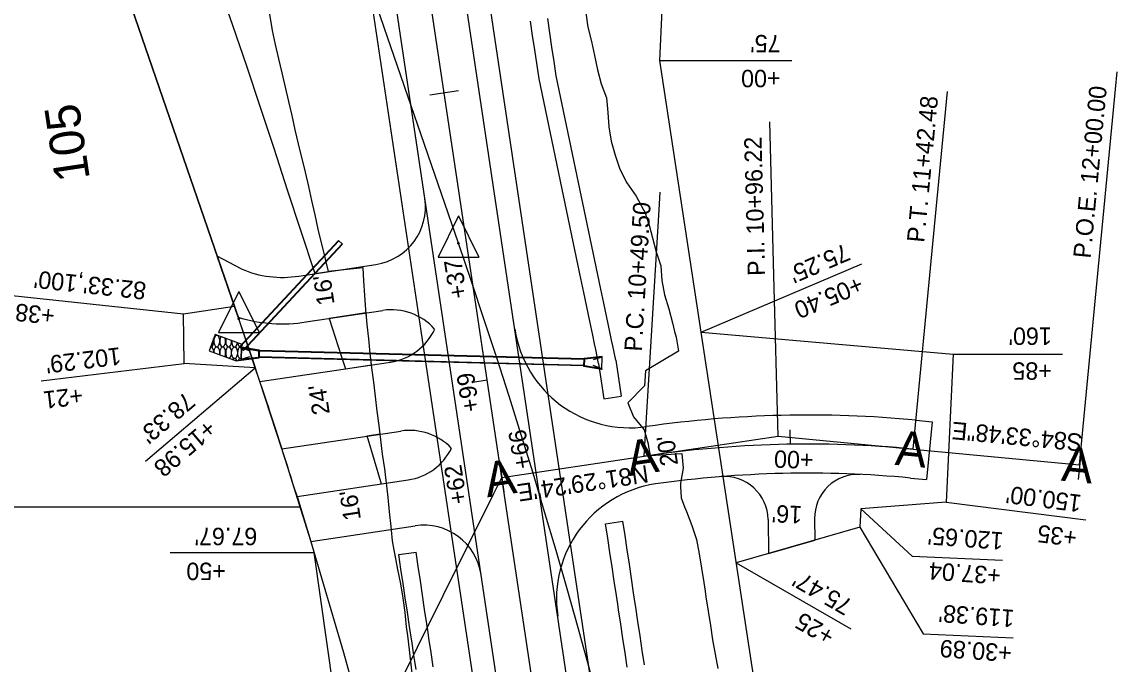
# Model space of a CAD drawing. Extents: x 609264 to 611265, y 427753 to 431566.
# Drawn here: x 610888.4 to 611265.4, y 428592 to 428813.2 of the extents above; entities that cross this region are included whole.
import ezdxf

# ---------------------------------------------------------------- set-up
doc = ezdxf.new("R2010")
doc.units = 0
for name, color, linetype in [('R_Drainage', 7, 'Continuous'), ('R_Drainage Stage 2', 7, 'Continuous'), ('R_Drive', 7, 'Continuous'), ('R_Drive Annot', 7, 'Continuous'), ('R_Drive Annot Stage 2', 7, 'Continuous'), ('R_Drive Stage 2', 7, 'Continuous'), ('R_Horz Alg', 7, 'Continuous'), ('R_Horz Alg Station', 7, 'Continuous'), ('R_Horz Alg Station Annot', 7, 'Continuous'), ('R_Horz Bearings', 7, 'Continuous'), ('R_Obliterate', 7, 'Continuous'), ('R_Proposed Const Limits', 7, 'Continuous'), ('R_Proposed Const Limits S2', 7, 'Continuous'), ('R_Proposed Road', 7, 'Continuous'), ('R_Proposed Road Stage 2', 7, 'Continuous'), ('R_Proposed Shoulder', 7, 'Continuous'), ('R_Proposed Shoulder Stage 2', 7, 'Continuous'), ('R_Restraining Conditions', 7, 'Continuous'), ('R_ROW', 7, 'Continuous'), ('R_ROW Annot', 7, 'Continuous'), ('R_Temp Easement', 7, 'Continuous'), ('S_EXIST_ROW', 7, 'Continuous')]:
    doc.layers.add(name, color=color, linetype=linetype)

msp = doc.modelspace()

# ---------------------------------------------------------------- linework, layer by layer
at = {"layer": 'R_Drainage'}
for p, q in [((610954.89, 428705.51), (610952.83, 428699.88)), ((610964.28, 428702.07), (610954.89, 428705.51)), ((610963.88, 428696.73), (610963.99, 428701.23)), ((610963.99, 428700.98), (610963.88, 428696.98)), ((610963.99, 428701.23), (610964.29, 428702.07)), ((610963.99, 428701.23), (610970.13, 428700.2)), ((610963.99, 428700.98), (610963.99, 428701.23)), ((610963.99, 428701.23), (610966.96, 428699.85)), ((610963.99, 428700.98), (610969.87, 428699.94)), ((610963.99, 428700.98), (610966.96, 428699.85)), ((610952.83, 428699.88), (610962.22, 428696.44)), ((610963.88, 428696.98), (610966.91, 428697.96)), ((610963.88, 428696.73), (610966.91, 428697.96)), ((610963.88, 428696.98), (610969.82, 428697.72)), ((610963.88, 428696.73), (610970.06, 428697.44)), ((610969.88, 428699.96), (610969.82, 428697.7)), ((610970.07, 428697.69), (610969.82, 428697.7)), ((610970.13, 428699.95), (610969.88, 428699.96)), ((610970.06, 428697.44), (610970.07, 428697.69)), ((611081.87, 428694.7), (610970.06, 428697.61)), ((610970.13, 428699.95), (610970.07, 428697.69)), ((611081.88, 428694.91), (610970.07, 428697.82)), ((611081.93, 428696.91), (610970.12, 428699.82)), ((610970.13, 428700.2), (610970.13, 428699.95)), ((611081.93, 428697.12), (610970.13, 428700.03)), ((611081.87, 428694.78), (611081.93, 428697.04)), ((611081.94, 428697.29), (611081.93, 428697.04)), ((611081.93, 428697.04), (611082.18, 428697.03)), ((611088.12, 428698), (611081.94, 428697.29)), ((611082.12, 428694.77), (611082.18, 428697.03)), ((611088.11, 428697.75), (611082.18, 428697.01)), ((611088.12, 428698), (611085.09, 428696.77)), ((611088.11, 428697.75), (611085.09, 428696.77)), ((611088.01, 428693.75), (611088.11, 428697.75)), ((611088.11, 428697.75), (611088.12, 428698)), ((610962.22, 428696.44), (610963.88, 428696.73)), ((610963.88, 428696.98), (610963.88, 428696.73)), ((611081.87, 428694.78), (611082.12, 428694.77)), ((611081.87, 428694.53), (611081.87, 428694.78)), ((611088, 428693.5), (611081.87, 428694.53)), ((611088.01, 428693.75), (611082.12, 428694.79)), ((611088.01, 428693.75), (611085.04, 428694.88)), ((611088, 428693.5), (611085.04, 428694.88)), ((611086.95, 428695.59), (611088.78, 428683.38)), ((611088.01, 428693.75), (611088, 428693.5)), ((611092.86, 428696.65), (611094.71, 428684.27)), ((611088.78, 428683.38), (611094.71, 428684.27)), ((611089.37, 428640.38), (611095.3, 428641.27))]:
    msp.add_line(p, q, dxfattribs=at)
for points in [[(611072.35, 428794.64), (611071.62, 428799.5), (611070.88, 428804.44), (611070.15, 428809.39), (611069.41, 428814.33)], [(611066.44, 428793.58), (611064.95, 428803.55), (611064.21, 428808.5), (611063.47, 428813.44)], [(611086.95, 428695.59), (611085.95, 428700.35), (611085.54, 428702.31), (611084.93, 428705.25), (611083.9, 428710.16), (611082.87, 428715.06), (611081.85, 428719.96), (611080.82, 428724.86), (611079.8, 428729.76), (611078.77, 428734.67), (611066.44, 428793.58)], [(611092.86, 428696.65), (611091.83, 428701.58), (611091.41, 428703.54), (611090.8, 428706.48), (611089.77, 428711.38), (611088.75, 428716.29), (611087.72, 428721.19), (611086.7, 428726.09), (611085.67, 428730.99), (611084.64, 428735.9), (611072.35, 428794.64)], [(611102.7, 428591.81), (611101.96, 428596.75), (611101.22, 428601.7), (611100.48, 428606.64), (611099.74, 428611.59), (611099.45, 428613.56), (611099, 428616.53), (611098.26, 428621.48), (611097.52, 428626.42), (611096.78, 428631.37), (611096.04, 428636.31), (611095.3, 428641.27)], [(611096.77, 428590.92), (611096.03, 428595.86), (611095.29, 428600.81), (611094.55, 428605.75), (611093.81, 428610.7), (611093.51, 428612.67), (611093.07, 428615.64), (611092.33, 428620.59), (611091.59, 428625.53), (611090.85, 428630.48), (611090.11, 428635.42), (611089.37, 428640.38)]]:
    msp.add_lwpolyline(points, dxfattribs=at)
for centre, start_param, end_param in [((610955.49, 428703.26), 2.962983, 9.234457), ((610955.49, 428707.26), 5.83754, 6.359902), ((610957.53, 428703.26), 3.842319, 8.355123), ((610953.45, 428699.26), 1.58016, 3.265491), ((610953.45, 428703.26), 6.169493, 8.293906), ((610955.49, 428699.26), 1.211214, 4.703043), ((610957.53, 428699.26), 0.814629, 5.099628), ((610959.57, 428699.26), 0.248071, 5.666186), ((610959.57, 428703.26), 4.258371, 7.939071), ((610961.61, 428703.26), 4.628634, 7.568808), ((610963.65, 428699.26), 2.804547, 6.518378), ((610963.65, 428703.26), 5.01425, 6.626432), ((610963.65, 428703.26), 0.343246, 0.410436), ((610961.61, 428695.26), 2.226876, 3.764608), ((610963.65, 428695.26), 2.909255, 4.005005)]:
    msp.add_ellipse(centre, major_axis=(0, -2), ratio=0.51, start_param=start_param, end_param=end_param, dxfattribs=at)
msp.add_ellipse((610961.61, 428699.26), major_axis=(0, -2), ratio=0.51, dxfattribs=at)
at = {"layer": 'R_Drainage Stage 2'}
for p, q in [((610997.4, 428737.94), (610963.32, 428701.26)), ((610997.52, 428737.83), (610963.44, 428701.15)), ((610998.62, 428736.81), (610964.54, 428700.13)), ((610998.74, 428736.69), (610964.66, 428700.02)), ((610997.4, 428737.94), (610998.74, 428736.69)), ((610963.32, 428701.26), (610964.66, 428700.02)), ((611018.16, 428629.71), (611024.09, 428630.61))]:
    msp.add_line(p, q, dxfattribs=at)
for points in [[(611024.08, 428590.16), (611023.34, 428595.1), (611022.6, 428600.04), (611022.3, 428602.02), (611021.86, 428604.99), (611021.12, 428609.93), (611020.38, 428614.88), (611019.64, 428619.82), (611018.9, 428624.77), (611018.16, 428629.71)], [(611030.01, 428591.04), (611029.27, 428595.99), (611028.53, 428600.93), (611028.24, 428602.91), (611027.79, 428605.88), (611027.05, 428610.82), (611026.31, 428615.77), (611025.57, 428620.71), (611024.83, 428625.66), (611024.09, 428630.61)]]:
    msp.add_lwpolyline(points, dxfattribs=at)
at = {"layer": 'R_Drive'}
for p, q in [((611196.24, 428676.02), (611201.77, 428675.5)), ((611201.77, 428675.5), (611199.87, 428655.59)), ((611194.35, 428656.11), (611199.87, 428655.59)), ((611145.29, 428641.87), (611145.48, 428630.11)), ((611161.29, 428642.13), (611161.41, 428634.72)), ((611145.48, 428630.11), (611161.41, 428634.72))]:
    msp.add_line(p, q, dxfattribs=at)
for centre, radius, start, end in [((611097.65, 428713.4), 40, 188.51, 278.51), ((611159.1, 428285.81), 391.97, 84.5634, 98.1447), ((611159.1, 428285.81), 371.97, 84.5634, 98.1251), ((611130.29, 428641.62), 15, 0.9351, 94.6293), ((611176.29, 428642.37), 15, 87.241, 180.9351), ((611112.45, 428614.5), 40, 98.51, 188.51)]:
    msp.add_arc(centre, radius, start, end, dxfattribs=at)
at = {"layer": 'R_Drive Stage 2'}
for p, q in [((610963.93, 428728.13), (610955.6, 428732.56)), ((610962.85, 428711.49), (610955.6, 428732.56)), ((610983.71, 428725.67), (611010.29, 428729.65)), ((610986.18, 428709.86), (611012.65, 428713.83)), ((610970.36, 428689.3), (611015.32, 428696.02)), ((610977.92, 428666.16), (610970.36, 428689.3)), ((610977.92, 428666.16), (611018.87, 428672.29)), ((610983.12, 428649.75), (611021.38, 428655.48)), ((610983.12, 428649.75), (610987.89, 428634.29)), ((610987.89, 428634.29), (611023.75, 428639.65))]:
    msp.add_line(p, q, dxfattribs=at)
for centre, radius, start, end in [((611007.33, 428749.43), 20, 278.51, 8.51), ((610977.99, 428760.46), 35.26, 246.4902, 279.3298), ((611015.61, 428694.05), 20, 41.877, 98.51), ((610977.99, 428760.46), 51.26, 252.8189, 279.3298), ((611012.36, 428715.8), 20, 278.51, 335.143), ((611021.83, 428652.51), 20, 43.6096, 98.51), ((611018.42, 428675.26), 20, 278.51, 333.4103), ((611026.71, 428619.87), 20, 8.51, 98.51)]:
    msp.add_arc(centre, radius, start, end, dxfattribs=at)
at = {"layer": 'R_Horz Alg'}
for p, q in [((611107.78, 428294.28), (610909.26, 429621.04)), ((611102.58, 428663.58), (611148.78, 428670.49)), ((611148.78, 428670.49), (611195.29, 428666.07)), ((611053.62, 428656.25), (611102.58, 428663.58)), ((611195.29, 428666.07), (611252.55, 428660.62))]:
    msp.add_line(p, q, dxfattribs=at)
msp.add_arc((611159.1, 428285.81), 381.97, 84.5634, 98.51, dxfattribs=at)
at = {"layer": 'R_Horz Alg Station'}
for points in [[(611252.55, 428660.62), (611264.87, 428790.03), (611265.44, 428796.01)], [(611028.85, 428788.04), (611038.74, 428789.52)], [(611195.29, 428666.07), (611202.02, 428736.75), (611207.01, 428789.17)], [(611148.78, 428670.49), (611147.3, 428725.88), (611145.88, 428778.81)], [(611102.58, 428663.58), (611107.75, 428748.46), (611108.12, 428754.58)], [(611043.65, 428689.14), (611048.59, 428689.88)], [(611152.79, 428672.73), (611152.87, 428667.73)], [(611253.03, 428665.6), (611252.08, 428655.64)], [(611052.88, 428661.2), (611054.36, 428651.31)], [(610928.44, 428404.22), (611050.9, 428650.77), (611053.62, 428656.25)]]:
    msp.add_lwpolyline(points, dxfattribs=at)
at = {"layer": 'R_Obliterate'}
for p, q in [((610978, 428795.6), (610976.8, 428800.47)), ((610979.2, 428790.72), (610978, 428795.6)), ((610989.34, 428746.74), (610988.27, 428751.63)), ((610993.06, 428731.05), (610992.81, 428732.09)), ((610993.99, 428727.21), (610993.06, 428731.05)), ((610989.22, 428726.5), (610993.99, 428727.21)), ((610989.22, 428726.5), (610993.99, 428727.21)), ((611006.94, 428712.97), (610994.21, 428711.07)), ((610994.21, 428711.07), (610998.34, 428698.17)), ((610998.34, 428698.17), (610999.76, 428693.7)), ((610999.76, 428693.7), (611008.8, 428695.05)), ((611011.71, 428671.22), (611007.15, 428670.53)), ((611007.15, 428670.53), (611007.45, 428669.6)), ((611012.07, 428654.08), (611013.92, 428654.36))]:
    msp.add_line(p, q, dxfattribs=at)
for points in [[(610882.37, 429038.56), (610887.37, 429024.62), (610892.25, 429010.47), (610897.14, 428996.31), (610902.07, 428982.17), (610907.05, 428967.98), (610912.02, 428953.85), (610916.96, 428939.72), (610921.8, 428925.53), (610926.59, 428911.33), (610931.46, 428897.15), (610936.41, 428883), (610941.29, 428868.88), (610946.18, 428854.7), (610951.1, 428840.46), (610956.02, 428826.29), (610960.93, 428812.12), (610965.73, 428798.1), (610970.48, 428783.88), (610975.1, 428769.66), (610979.74, 428755.4), (610984.4, 428741.15), (610989.09, 428726.9), (610989.22, 428726.5)], [(610882.37, 429038.56), (610887.37, 429024.62), (610892.25, 429010.47), (610897.14, 428996.31), (610902.07, 428982.17), (610907.05, 428967.98), (610912.02, 428953.85), (610916.96, 428939.72), (610921.8, 428925.53), (610926.59, 428911.33), (610931.46, 428897.15), (610936.41, 428883), (610941.29, 428868.88), (610946.18, 428854.7), (610951.1, 428840.46), (610956.02, 428826.29), (610960.93, 428812.12), (610965.73, 428798.1), (610970.48, 428783.88), (610975.1, 428769.66), (610979.74, 428755.4), (610984.4, 428741.15), (610989.09, 428726.9), (610989.22, 428726.5)], [(610976.8, 428800.47), (610975.72, 428805.37), (610974.71, 428810.27), (610973.84, 428815.2), (610972.82, 428820.1), (610971.78, 428825), (610970.8, 428829.91), (610969.82, 428834.82), (610968.75, 428839.71)], [(610993.99, 428727.21), (610993.06, 428731.05), (610992.81, 428732.09), (610990.43, 428741.85), (610989.34, 428746.74), (610988.27, 428751.63), (610987.18, 428756.53), (610986.01, 428761.41), (610983.64, 428771.16), (610982.51, 428776.05), (610981.39, 428780.94), (610980.29, 428785.83), (610979.2, 428790.72), (610978, 428795.6), (610976.8, 428800.47), (610975.72, 428805.37), (610974.71, 428810.27), (610973.84, 428815.2)], [(610983.64, 428771.16), (610982.51, 428776.05), (610981.39, 428780.94), (610980.29, 428785.83), (610979.2, 428790.72)], [(610988.27, 428751.63), (610987.18, 428756.53), (610986.01, 428761.41), (610983.64, 428771.16)], [(610992.81, 428732.09), (610990.43, 428741.85), (610989.34, 428746.74)], [(611008.8, 428695.05), (611008.35, 428699.03), (611007.78, 428704), (611007.28, 428708.98), (611006.94, 428712.97)], [(611013.92, 428654.36), (611013.3, 428659.32), (611012.56, 428664.27), (611011.95, 428669.23), (611011.71, 428671.22)], [(611007.45, 428669.6), (611011.81, 428654.95), (611012.07, 428654.08)], [(611013.92, 428654.36), (611013.92, 428654.36)]]:
    msp.add_lwpolyline(points, dxfattribs=at)
at = {"layer": 'R_Proposed Const Limits'}
for points in [[(611082.57, 428816.3), (611083.19, 428811.34), (611084.44, 428806.47), (611085.58, 428801.58), (611086.54, 428796.67), (611087.84, 428791.81), (611089.61, 428787.02), (611090.11, 428782.04), (611090.46, 428777.04), (611091.26, 428772.1), (611092.62, 428767.25), (611094.21, 428762.43), (611096.66, 428757.74), (611099.88, 428753.17), (611102.39, 428748.49), (611102.92, 428747.49), (611104.17, 428743.71), (611104.32, 428743.23), (611105.54, 428738.85), (611106.76, 428733.97), (611108.35, 428729.16), (611108.69, 428724.15), (611109.67, 428719.24), (611111.14, 428714.41), (611112.36, 428709.53), (611113.1, 428706.61), (611113.62, 428704.67), (611114.5, 428699.74), (611103.07, 428692.98), (611102.78, 428687.88), (611097.03, 428681.96), (611098.97, 428677.2), (611102.62, 428672.69), (611103.95, 428667.83), (611104.17, 428666.87), (611104.66, 428663.89), (611115.62, 428664.52), (611116.08, 428659.53), (611115.12, 428654.33), (611115.19, 428653.1), (611115.36, 428649.32)], [(611115.36, 428649.32), (611116.55, 428646.17), (611117.16, 428644.55), (611117.17, 428644.53), (611119.02, 428639.75), (611120.61, 428634.93), (611121.55, 428630.02), (611122.34, 428625.08), (611123.13, 428620.14), (611123.58, 428617.17), (611123.89, 428615.2), (611124.65, 428610.26), (611125.42, 428605.32), (611126.19, 428600.38), (611127.06, 428595.45), (611127.97, 428590.53)]]:
    msp.add_lwpolyline(points, dxfattribs=at)
at = {"layer": 'R_Proposed Const Limits S2'}
msp.add_lwpolyline([(611028.03, 428542.72), (611021.49, 428599.88), (611021.21, 428601.85), (611020.86, 428604.84), (611020.29, 428609.81), (611019.71, 428614.78), (611018.84, 428619.7), (611017.87, 428624.61), (611016.9, 428629.53), (611016.57, 428631.21), (611015.98, 428634.45), (611015.62, 428638.2), (611015.5, 428639.43), (611014.98, 428644.41), (611014.45, 428649.38), (611014.02, 428653.39), (611013.92, 428654.36), (611013.3, 428659.32), (611012.56, 428664.27), (611011.95, 428669.23), (611011.35, 428674.2), (611010.75, 428679.16), (611010.16, 428684.13), (611009.51, 428689.09), (611008.91, 428694.05), (611008.35, 428699.03), (611007.78, 428704), (611007.28, 428708.98), (611006.86, 428713.97), (611006.47, 428718.97), (611006.11, 428723.97), (611005.88, 428728.5), (610993.99, 428727.21), (610993.99, 428727.22), (610993.06, 428731.05), (610992.81, 428732.09), (610990.43, 428741.85), (610989.34, 428746.74), (610988.27, 428751.63), (610987.18, 428756.53), (610986.01, 428761.41), (610983.64, 428771.16), (610982.51, 428776.05), (610981.39, 428780.94), (610980.29, 428785.83), (610979.2, 428790.72), (610978, 428795.6), (610976.8, 428800.47), (610975.72, 428805.37), (610974.71, 428810.27), (610973.84, 428815.2)], dxfattribs=at)
at = {"layer": 'R_Proposed Road'}
for p, q in [((611100.64, 428423.11), (610921.13, 429622.82)), ((611041.57, 428655.73), (610897.4, 429619.26))]:
    msp.add_line(p, q, dxfattribs=at)
at = {"layer": 'R_Proposed Road Stage 2'}
msp.add_line((611095.92, 428292.51), (611041.57, 428655.73), dxfattribs=at)
at = {"layer": 'R_Proposed Shoulder'}
for p, q in [((611112.77, 428396.14), (610929.04, 429624)), ((611025.84, 428706.82), (610889.48, 429618.08))]:
    msp.add_line(p, q, dxfattribs=at)
at = {"layer": 'R_Proposed Shoulder Stage 2'}
msp.add_line((611073.21, 428390.22), (611025.84, 428706.82), dxfattribs=at)
at = {"layer": 'R_Restraining Conditions'}
for p, q in [((610794.84, 429199.86), (610963.05, 428710.9)), ((610984.25, 428646.07), (609527.71, 428646.07))]:
    msp.add_line(p, q, dxfattribs=at)
msp.add_arc((608833.71, 427978.36), 2251.83, 17.24879, 18.98444, dxfattribs=at)
at = {"layer": 'R_ROW'}
for points in [[(611107.97, 428799.88), (611125.91, 429186.79), (611015.56, 429741.88)], [(611143.3, 428299.6), (611160.86, 428351.77), (611164.45, 428429.15), (611122.21, 428706.36), (611107.97, 428799.88)], [(610968.76, 428694.1), (610944.32, 428695.51), (610944.07, 428712.66), (610961.55, 428715.28)], [(611064.18, 428287.76), (611031.16, 428333.38), (610989.06, 428630.42)]]:
    msp.add_lwpolyline(points, dxfattribs=at)
at = {"layer": 'R_ROW Annot'}
for p, q in [((611107.97, 428799.88), (611153.49, 428799.88)), ((611122.21, 428706.36), (611177.58, 428729.88)), ((610881.83, 428719.36), (610944.07, 428712.66)), ((611209.05, 428698.72), (611246.66, 428698.72)), ((610895.04, 428689.52), (610944.32, 428695.51)), ((610930.93, 428661.96), (610968.76, 428694.1)), ((611206.56, 428647.79), (611254.63, 428641.68)), ((610939.42, 428630.42), (610989.06, 428630.42)), ((611134.33, 428626.87), (611173.76, 428604.12))]:
    msp.add_line(p, q, dxfattribs=at)
for points in [[(611177.23, 428645.47), (611194.92, 428629.15), (611225.96, 428627.76)], [(611176.88, 428639.2), (611198.65, 428602.46), (611229.7, 428601.07)]]:
    msp.add_lwpolyline(points, dxfattribs=at)
at = {"layer": 'R_Temp Easement'}
msp.add_lwpolyline([(611122.21, 428706.36), (611209.05, 428698.72), (611206.56, 428647.79), (611177.23, 428645.47), (611176.88, 428639.2), (611134.33, 428626.87)], dxfattribs=at)
at = {"layer": 'S_EXIST_ROW'}
for p, q in [((611038.7, 428736.93), (610840.72, 429312.43)), ((610963.05, 428710.9), (610794.84, 429199.86)), ((611038.73, 428746.38), (611031.68, 428732.2)), ((611038.73, 428746.38), (611045.7, 428732.2)), ((611038.7, 428736.93), (611038.7, 428736.93)), ((611031.68, 428732.2), (611045.7, 428732.2)), ((610963.08, 428720.36), (610956.03, 428706.17)), ((610963.08, 428720.36), (610970.06, 428706.17)), ((610963.05, 428710.9), (610963.05, 428710.9)), ((610956.03, 428706.17), (610970.06, 428706.17))]:
    msp.add_line(p, q, dxfattribs=at)
for centre, radius in [((611038.7, 428736.93), 0.24), ((611038.7, 428736.93), 0.12), ((610963.05, 428710.9), 0.24), ((610963.05, 428710.9), 0.12)]:
    msp.add_circle(centre, radius, dxfattribs=at)
for radius in [2331.83, 2251.83]:
    msp.add_arc((608833.71, 427978.36), radius, 357.21778, 18.98444, dxfattribs=at)

# ---------------------------------------------------------------- texts
at = {"layer": 'R_Drive Annot'}
for s, rotation, p in [('+66', 99.0593, (611063.86, 428659.72)), ("20'", 98.6267, (611114.33, 428660.73)), ('+00', 177.9932, (611161.05, 428665.21)), ("16'", 177.6558, (611157.15, 428646.43))]:
    msp.add_text(s, height=6, rotation=rotation, dxfattribs=at).set_placement(p)
at = {"layer": 'R_Drive Annot Stage 2'}
for s, rotation, p in [('+37', 99.0593, (611041.71, 428718.39)), ("16'", 98.6267, (610996.07, 428716.06)), ('+99', 99.0593, (611046.03, 428679.32)), ("24'", 98.6267, (610994.42, 428678.32)), ('+62', 99.0593, (611041.75, 428647.57)), ("16'", 98.6267, (611005.14, 428641.92))]:
    msp.add_text(s, height=6, rotation=rotation, dxfattribs=at).set_placement(p)
at = {"layer": 'R_Horz Alg'}
for rotation, p in [(354.5634, (611188.75, 428660.66)), (8.51, (611097.53, 428656.76)), (354.5634, (611246.01, 428655.21)), (8.51, (611048.58, 428649.43))]:
    msp.add_text('A', height=12, rotation=rotation, dxfattribs=at).set_placement(p)
at = {"layer": 'R_Horz Alg Station Annot'}
for s, height, rotation, p in [('P.O.E. 12+00.00', 6, 84.5634, (611256.29, 428731.58)), ('105', 12, 98.51, (610911.84, 428759.16)), ('P.T. 11+42.48', 6, 84.5634, (611199.03, 428737.03)), ('P.I. 10+96.22', 6, 91.5367, (611144.3, 428725.8)), ('P.C. 10+49.50', 6, 86.5148, (611101.77, 428699.56))]:
    msp.add_text(s, height=height, rotation=rotation, dxfattribs=at).set_placement(p)
at = {"layer": 'R_Horz Bearings'}
for s, rotation, p in [('S84%%d33\'48"E', 174.5634, (611253.69, 428671.23)), ('N81%%d29\'24"E', 188.51, (611103.6, 428660.63))]:
    msp.add_text(s, height=6, rotation=rotation, dxfattribs=at).set_placement(p)
at = {"layer": 'R_ROW Annot'}
for s, rotation, p in [("75'", 180, (611149.6, 428808.7)), ('+00', 180, (611149.6, 428796.7)), ("75.25'", 203.0178, (611171.77, 428736.99)), ("82.33',100'", 173.8608, (610931.43, 428723.47)), ('+05.40', 203.0178, (611176.47, 428725.95)), ('+38', 173.8608, (610899.98, 428714.79)), ("160'", 180, (611242.99, 428707.95)), ("102.29'", 186.9307, (610922.14, 428701.18)), ('+85', 180, (611242.99, 428695.95)), ('+21', 186.9307, (610909.04, 428687.5)), ("78.33'", 220.3394, (610944.73, 428686.05)), ('+15.98', 220.3394, (610952.14, 428676.6)), ("150.00'", 172.7535, (611253.46, 428650.21)), ("67.67'", 180, (610969.45, 428638.96)), ("120.65'", 175.8696, (611226.49, 428637.35)), ('+35', 172.7535, (611251.95, 428638.31)), ('+50', 180, (610958.63, 428626.96)), ('+37.04', 175.8696, (611225.62, 428625.38)), ("75.47'", 150.0186, (611174.79, 428613.71)), ("119.38'", 175.8696, (611230.22, 428610.65)), ('+25', 150.0186, (611168.79, 428603.32)), ('+30.89', 175.8696, (611229.36, 428598.68))]:
    msp.add_text(s, height=6, rotation=rotation, dxfattribs=at).set_placement(p)

doc.saveas('drawing.dxf')
